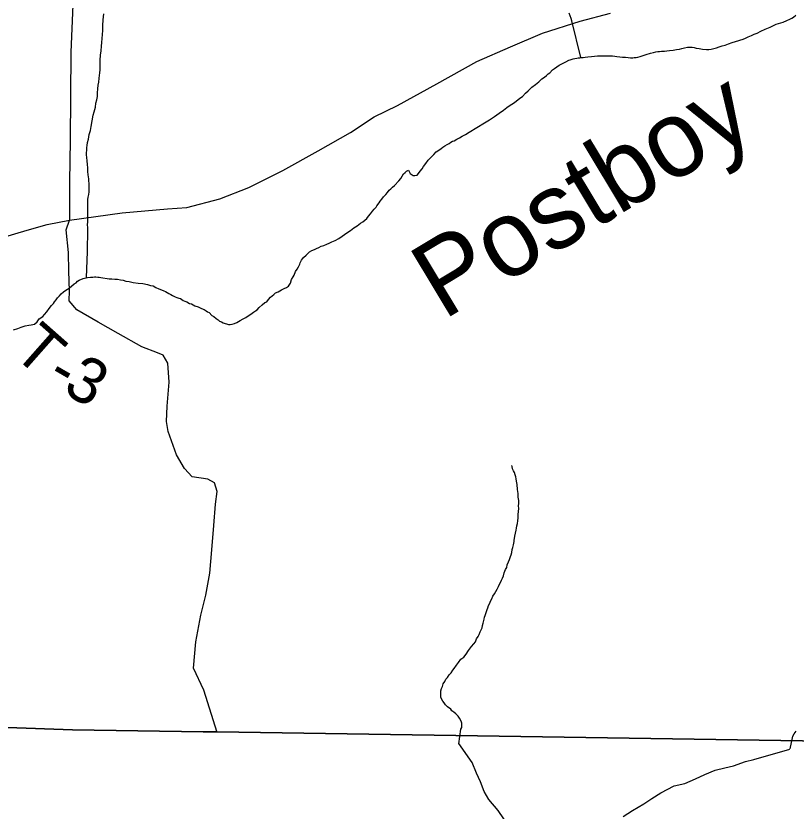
# Model space of a CAD drawing. Extents: x -14196 to 143, y -6096 to 28.
# Drawn here: x 59.622 to 60.591, y 18.723 to 19.711 of the extents above; entities that cross this region are included whole.
import ezdxf

# ---------------------------------------------------------------- set-up
doc = ezdxf.new("R2010")
doc.units = 0
for name, color, linetype in [('GM_X_Corporation', 7, 'Continuous'), ('GM_X_County_Road', 7, 'Continuous'), ('GM_X_Minor_River', 7, 'Continuous'), ('GM_X_Minor_River_Text', 7, 'Continuous'), ('GM_X_Township_Road', 7, 'Continuous'), ('GM_X_Township_Road_Text', 7, 'Continuous')]:
    doc.layers.add(name, color=color, linetype=linetype)

msp = doc.modelspace()

# ---------------------------------------------------------------- linework, layer by layer
at = {"layer": 'GM_X_Corporation'}
for points in [[(58.10282, 23.69854), (58.10282, 18.87106), (58.91817, 18.84869), (59.19654, 18.84209), (59.69267, 18.82448), (59.85497, 18.82206), (59.87217, 18.8218), (60.89542, 18.80611)], [(58.10282, 23.69854), (58.10282, 18.87106), (58.91817, 18.84869), (59.19654, 18.84209), (59.69267, 18.82448), (59.85497, 18.82206), (59.87217, 18.8218), (60.89542, 18.80611)], [(60.89542, 18.80611), (59.87217, 18.8218), (59.85497, 18.82206), (59.69267, 18.82448), (59.19654, 18.84209), (58.91817, 18.84869), (58.10282, 18.87106), (58.10282, 16.89854), (64.90282, 16.89854)], [(60.89542, 18.80611), (59.87217, 18.8218), (59.85497, 18.82206), (59.69267, 18.82448), (59.19654, 18.84209), (58.91817, 18.84869), (58.10282, 18.87106), (58.10282, 16.89854), (62.31172, 16.89854)]]:
    msp.add_lwpolyline(points, dxfattribs=at)
at = {"layer": 'GM_X_County_Road'}
for points in [[(59.69407, 19.75527), (59.69062, 19.66662), (59.6896, 19.55673), (59.68899, 19.50578), (59.68868, 19.45788)], [(59.60114, 19.43513), (59.6362, 19.44515), (59.66109, 19.45224), (59.68868, 19.45788), (59.75416, 19.46676), (59.81062, 19.47161), (59.83451, 19.47336), (59.87562, 19.48428), (59.91135, 19.49848), (59.95373, 19.51931), (59.99754, 19.54398), (60.03799, 19.56667), (60.06712, 19.58602), (60.096, 19.60005), (60.14507, 19.62712), (60.19487, 19.65498), (60.23656, 19.67312), (60.27639, 19.69008), (60.3231, 19.70492), (60.36082, 19.71498)]]:
    msp.add_lwpolyline(points, dxfattribs=at)
at = {"layer": 'GM_X_Minor_River'}
for points in [[(59.70979, 19.38616), (59.71132, 19.41879), (59.71129, 19.42145), (59.71126, 19.42335), (59.71122, 19.42677), (59.71117, 19.43095), (59.71152, 19.43399), (59.71148, 19.43703), (59.71143, 19.44159), (59.71176, 19.44539), (59.71173, 19.44805), (59.7113, 19.45223), (59.71164, 19.45527), (59.71161, 19.45793), (59.71156, 19.46249), (59.71151, 19.46629), (59.71148, 19.46933), (59.71145, 19.47161), (59.71142, 19.47427), (59.71175, 19.47769), (59.71171, 19.48111), (59.71169, 19.48339), (59.71203, 19.48644), (59.71275, 19.48948), (59.71309, 19.49291), (59.71342, 19.49709), (59.71338, 19.50051), (59.71334, 19.50355), (59.71293, 19.5062), (59.7129, 19.50887), (59.71249, 19.51152), (59.71208, 19.51418), (59.71165, 19.51797), (59.71159, 19.52291), (59.71117, 19.52671), (59.71074, 19.53126), (59.7103, 19.53544), (59.70988, 19.53886), (59.70985, 19.54152), (59.7102, 19.54456), (59.71016, 19.54798), (59.71088, 19.55065), (59.71122, 19.55407), (59.71231, 19.55826), (59.71338, 19.56397), (59.71484, 19.56893), (59.71554, 19.57426), (59.71841, 19.58797), (59.7195, 19.59216), (59.72023, 19.59521), (59.72095, 19.59825), (59.72165, 19.6032), (59.72274, 19.60739), (59.72345, 19.6112), (59.72378, 19.61577), (59.7241, 19.62071), (59.72442, 19.62527), (59.72514, 19.62908), (59.72546, 19.63402), (59.72618, 19.63745), (59.72652, 19.64088), (59.72685, 19.64468), (59.7268, 19.64886), (59.72676, 19.65266), (59.72709, 19.65646), (59.7274, 19.66255), (59.72809, 19.66825), (59.7284, 19.67396), (59.72911, 19.67852), (59.72943, 19.68347), (59.72975, 19.68841), (59.73007, 19.69336), (59.73038, 19.69944), (59.73067, 19.70666), (59.73134, 19.71389)], [(60.32369, 19.65972), (60.31251, 19.70536), (60.31172, 19.7084), (60.31054, 19.71142), (60.30936, 19.71483)], [(60.50729, 19.6769), (60.51183, 19.67847), (60.51599, 19.67965), (60.52544, 19.68278), (60.52847, 19.68395), (60.53187, 19.68551), (60.53565, 19.68706), (60.53905, 19.68862), (60.54283, 19.69017), (60.54736, 19.6925), (60.55264, 19.69483), (60.55907, 19.69756), (60.56662, 19.70143), (60.57532, 19.7038), (60.57986, 19.70574), (60.58326, 19.7073), (60.58589, 19.70884), (60.58816, 19.71001), (60.59079, 19.71231)], [(60.15788, 19.55181), (60.16015, 19.55298), (60.16241, 19.55452), (60.16467, 19.55568), (60.16656, 19.55646), (60.16996, 19.5584), (60.17298, 19.55995), (60.17637, 19.56188), (60.18052, 19.5642), (60.18505, 19.56691), (60.20427, 19.5785), (60.2103, 19.58236), (60.21671, 19.58661), (60.22236, 19.59084), (60.22763, 19.59432), (60.23215, 19.59778), (60.23629, 19.60048), (60.24006, 19.60318), (60.24345, 19.60549), (60.24608, 19.6078), (60.24947, 19.61012), (60.25135, 19.61127), (60.2551, 19.61549), (60.25848, 19.61857), (60.26299, 19.62279), (60.26751, 19.62626), (60.27164, 19.62972), (60.2754, 19.63317), (60.27879, 19.63549), (60.28104, 19.63741), (60.2833, 19.63933), (60.28518, 19.64087), (60.28856, 19.64433), (60.29119, 19.64625), (60.29421, 19.64818), (60.29684, 19.65011), (60.30024, 19.65204), (60.30288, 19.65321), (60.30515, 19.65437), (60.30892, 19.65631), (60.31081, 19.65671), (60.31421, 19.65826), (60.31649, 19.65866), (60.31876, 19.65907), (60.32066, 19.65947), (60.32255, 19.65949), (60.32445, 19.65988), (60.32673, 19.65991), (60.32938, 19.66031), (60.33241, 19.66072), (60.33696, 19.66115), (60.34076, 19.66157), (60.34455, 19.66199), (60.34797, 19.66202), (60.35101, 19.66205), (60.36012, 19.66176), (60.36316, 19.66179), (60.3662, 19.66144), (60.36848, 19.66108), (60.37229, 19.66074), (60.37571, 19.66039), (60.37951, 19.66005), (60.38255, 19.6597), (60.3856, 19.65935), (60.38825, 19.65938), (60.39015, 19.65978), (60.39243, 19.6598), (60.3947, 19.6602), (60.39735, 19.66099), (60.40113, 19.66217), (60.40491, 19.66373), (60.41021, 19.6653), (60.414, 19.6661), (60.41702, 19.66688), (60.41968, 19.66729), (60.42158, 19.66731), (60.42423, 19.66772), (60.42765, 19.66775), (60.43068, 19.66816), (60.43409, 19.66858), (60.43865, 19.669), (60.44281, 19.6698), (60.44623, 19.67022), (60.44925, 19.67101), (60.45266, 19.6718), (60.45645, 19.6726), (60.45949, 19.67263), (60.46215, 19.67265), (60.46443, 19.6723), (60.4671, 19.67156), (60.4709, 19.67084), (60.47509, 19.67012), (60.48003, 19.66979), (60.48269, 19.66982), (60.48572, 19.67023), (60.48913, 19.67102), (60.49216, 19.67181), (60.49556, 19.67299), (60.49935, 19.67416), (60.50313, 19.67534), (60.50729, 19.6769)], [(59.88825, 19.3279), (59.8909, 19.32869), (59.89355, 19.32948), (59.89658, 19.33065), (59.90073, 19.33297), (59.9045, 19.33491), (59.9079, 19.33684), (59.91091, 19.33878), (59.91392, 19.34109), (59.91731, 19.3434), (59.91995, 19.34495), (59.92183, 19.34649), (59.92446, 19.34918), (59.92822, 19.35263), (59.9316, 19.35533), (59.93387, 19.35611), (59.93611, 19.35918), (59.93836, 19.36186), (59.94062, 19.36378), (59.9425, 19.36532), (59.94475, 19.36724), (59.94777, 19.3688), (59.95192, 19.37112), (59.95532, 19.37267), (59.95834, 19.37423), (59.96098, 19.37577), (59.96322, 19.37959), (59.96468, 19.38417), (59.96654, 19.38723), (59.96765, 19.38952), (59.9695, 19.39372), (59.97174, 19.39678), (59.97323, 19.39984), (59.97471, 19.40289), (59.97545, 19.4048), (59.97693, 19.40786), (59.97955, 19.4113), (59.98255, 19.41437), (59.9848, 19.4163), (59.98706, 19.41822), (59.98969, 19.42015), (59.9931, 19.42132), (59.99574, 19.42249), (59.99839, 19.42366), (60.00141, 19.4252), (60.00481, 19.42638), (60.00821, 19.42794), (60.01123, 19.42911), (60.01463, 19.43066), (60.01879, 19.4326), (60.02332, 19.43493), (60.02746, 19.43763), (60.03311, 19.44187), (60.03763, 19.44495), (60.04177, 19.44804), (60.04592, 19.45074), (60.05006, 19.45382), (60.05307, 19.45575), (60.05571, 19.45768), (60.05796, 19.45998), (60.06021, 19.46267), (60.06245, 19.46573), (60.06507, 19.4688), (60.06732, 19.47148), (60.06957, 19.47378), (60.07069, 19.47569), (60.0733, 19.47914), (60.07479, 19.48143), (60.07666, 19.48373), (60.07891, 19.4868), (60.08153, 19.48948), (60.08378, 19.49216), (60.08603, 19.49485), (60.0879, 19.49677), (60.09016, 19.49869), (60.09241, 19.50061), (60.09766, 19.50637), (60.10028, 19.50943), (60.10215, 19.51249), (60.10363, 19.51517), (60.10551, 19.51709), (60.10739, 19.51863), (60.10965, 19.51979), (60.11198, 19.51563), (60.11543, 19.51339), (60.11771, 19.51303), (60.12074, 19.51382), (60.12223, 19.51574), (60.12448, 19.51842), (60.12672, 19.52148), (60.12859, 19.52454), (60.1312, 19.52799), (60.13419, 19.5322), (60.13794, 19.53603), (60.14132, 19.53949), (60.14432, 19.54256), (60.14771, 19.54487), (60.15035, 19.5468), (60.15261, 19.54834), (60.15487, 19.54988), (60.15788, 19.55181)], [(59.61943, 19.3213), (59.62473, 19.32326), (59.62888, 19.32482), (59.6338, 19.32639), (59.63835, 19.3272), (59.64138, 19.32761), (59.64328, 19.32801), (59.64555, 19.32842), (59.64855, 19.33149), (59.65117, 19.33531), (59.65569, 19.33802), (59.65794, 19.34033), (59.66056, 19.34377), (59.66355, 19.34799), (59.66654, 19.35182), (59.66879, 19.35412), (59.67029, 19.35641), (59.67216, 19.35872), (59.67402, 19.36139), (59.67627, 19.3637), (59.67853, 19.366), (59.68153, 19.36869), (59.68417, 19.37062), (59.68643, 19.37216), (59.68831, 19.37332), (59.69471, 19.37871), (59.69697, 19.37988), (59.69885, 19.38179), (59.70073, 19.38295), (59.70564, 19.38528), (59.71133, 19.38649), (59.71474, 19.3869), (59.71778, 19.38693), (59.71967, 19.38733), (59.72157, 19.38735), (59.72385, 19.387), (59.72575, 19.38702), (59.72766, 19.38627), (59.73793, 19.38486), (59.74135, 19.3849), (59.74515, 19.38456), (59.74857, 19.38421), (59.752, 19.38349), (59.75542, 19.38314), (59.75885, 19.38204), (59.76304, 19.38133), (59.76799, 19.38024), (59.77408, 19.37954), (59.77978, 19.37884), (59.78549, 19.37776), (59.7893, 19.37666), (59.79273, 19.37593), (59.79617, 19.37407), (59.79961, 19.37259), (59.80304, 19.3711), (59.80609, 19.36999), (59.80801, 19.36887), (59.80992, 19.36775), (59.81221, 19.36663), (59.81451, 19.36514), (59.8168, 19.36402), (59.81986, 19.36253), (59.82214, 19.3618), (59.82481, 19.36069), (59.82672, 19.36033), (59.82978, 19.35808), (59.83208, 19.35696), (59.83436, 19.35623), (59.8378, 19.35436), (59.84047, 19.35363), (59.84468, 19.35139), (59.84849, 19.34991), (59.85269, 19.34806), (59.85613, 19.34657), (59.85842, 19.34507), (59.86034, 19.34395), (59.86225, 19.34283), (59.86571, 19.33945), (59.868, 19.33795), (59.87107, 19.33533), (59.87337, 19.33383), (59.87529, 19.33233), (59.87758, 19.33121), (59.87949, 19.33009), (59.88635, 19.32827), (59.88825, 19.3279)], [(60.24459, 19.1294), (60.24416, 19.13358), (60.24375, 19.13623), (60.24295, 19.13888), (60.24217, 19.14115), (60.24137, 19.14419), (60.2402, 19.14645), (60.23904, 19.14872), (60.23862, 19.15176), (60.23823, 19.15251), (60.23823, 19.15289)], [(60.17231, 18.80698), (60.17494, 18.82513), (60.17605, 18.82742), (60.17602, 18.82932), (60.17598, 18.83274), (60.17519, 18.83539), (60.17325, 18.83879), (60.1717, 18.84143), (60.16863, 18.84444), (60.16633, 18.84632), (60.16365, 18.84819), (60.16248, 18.85008), (60.15827, 18.85308), (60.15558, 18.85571), (60.15403, 18.85797), (60.15249, 18.86024), (60.15015, 18.86477), (60.15006, 18.87275), (60.15078, 18.87579), (60.15189, 18.87846), (60.15299, 18.88151), (60.15485, 18.88457), (60.15634, 18.88725), (60.15821, 18.88955), (60.16045, 18.89299), (60.1627, 18.89529), (60.16494, 18.89873), (60.16644, 18.90065), (60.16942, 18.90486), (60.17204, 18.90792), (60.17503, 18.91213), (60.17842, 18.91483), (60.18141, 18.91866), (60.1844, 18.92287), (60.18813, 18.92784), (60.19113, 18.93129), (60.193, 18.93397), (60.19448, 18.93741), (60.19634, 18.94046), (60.19745, 18.94276), (60.19893, 18.94619), (60.20004, 18.94886), (60.20153, 18.95115), (60.20187, 18.9542), (60.2026, 18.95686), (60.20296, 18.95877), (60.20368, 18.96181), (60.20441, 18.96448), (60.20514, 18.96639), (60.20587, 18.96905), (60.2066, 18.97134), (60.20771, 18.97401), (60.20845, 18.97592), (60.20917, 18.97897), (60.21065, 18.98202), (60.21176, 18.98431), (60.21325, 18.98737), (60.21473, 18.99042), (60.21659, 18.99348), (60.21846, 18.99616), (60.21994, 18.99921), (60.22142, 19.00265), (60.22551, 19.01029), (60.22661, 19.01296), (60.22772, 19.01563), (60.22844, 19.01943), (60.23028, 19.02363), (60.23177, 19.02631), (60.23249, 19.02935), (60.23397, 19.03317), (60.23545, 19.03622), (60.23655, 19.03965), (60.23728, 19.04194), (60.238, 19.04499), (60.23872, 19.04841), (60.23945, 19.05108), (60.24017, 19.05451), (60.24088, 19.05831), (60.24124, 19.06022), (60.24159, 19.06212), (60.24194, 19.06516), (60.24265, 19.06897), (60.24337, 19.0724), (60.2441, 19.07506), (60.24445, 19.07773), (60.24517, 19.08077), (60.24551, 19.0842), (60.24622, 19.088), (60.24617, 19.09218), (60.24651, 19.09561), (60.24685, 19.09941), (60.24642, 19.10282), (60.24677, 19.10549), (60.24673, 19.10929), (60.24592, 19.11346), (60.24586, 19.11802), (60.24505, 19.12295), (60.24459, 19.1294)], [(60.58382, 18.80081), (60.58709, 18.81677), (60.58896, 18.81945), (60.5912, 18.82289)], [(60.27951, 18.62107), (60.26605, 18.63138), (60.2599, 18.64271), (60.24958, 18.65515), (60.24267, 18.66572), (60.23688, 18.67971), (60.23563, 18.69411), (60.23403, 18.70396), (60.22827, 18.71378), (60.22099, 18.72434), (60.20952, 18.73791), (60.20376, 18.74773), (60.19912, 18.75984), (60.19412, 18.77042), (60.18871, 18.78366), (60.17235, 18.80727)], [(60.3763, 18.71674), (60.38798, 18.72402), (60.40193, 18.73247), (60.41209, 18.73899), (60.4234, 18.74627), (60.43961, 18.75473), (60.45322, 18.75786), (60.46642, 18.76364), (60.47774, 18.76903), (60.49057, 18.77443), (60.50266, 18.77717), (60.51362, 18.7799), (60.52835, 18.78494), (60.53855, 18.78766), (60.58361, 18.80059)]]:
    msp.add_lwpolyline(points, dxfattribs=at)
at = {"layer": 'GM_X_Township_Road'}
msp.add_lwpolyline([(59.87237, 18.82126), (59.85553, 18.87374), (59.8429, 18.90117), (59.84587, 18.93393), (59.85187, 18.96677), (59.85808, 18.99162), (59.86308, 19.01912), (59.86577, 19.04807), (59.86804, 19.07815), (59.87003, 19.1048), (59.87229, 19.12045), (59.86898, 19.13139), (59.86051, 19.13573), (59.84107, 19.13866), (59.83169, 19.14906), (59.82176, 19.16629), (59.81154, 19.19492), (59.80933, 19.20741), (59.80998, 19.22643), (59.81264, 19.25652), (59.81091, 19.28005), (59.80535, 19.28979), (59.79804, 19.29302), (59.77849, 19.30051), (59.74921, 19.31688), (59.72454, 19.33108), (59.69795, 19.34636), (59.68855, 19.35753), (59.68862, 19.37007), (59.688, 19.39439), (59.68742, 19.41756), (59.68481, 19.44562), (59.68868, 19.45788)], dxfattribs=at)

# ---------------------------------------------------------------- texts
at = {"layer": 'GM_X_Minor_River_Text'}
msp.add_text('Postboy', height=0.09465, rotation=31.0201, dxfattribs=at).set_placement((60.15308, 19.33285))
at = {"layer": 'GM_X_Township_Road_Text'}
for s, rotation, p in [('T', 318.56292, (59.61635, 19.29153)), ('3', 330.25485, (59.67869, 19.2444)), ('-', 330.03352, (59.65827, 19.25618))]:
    msp.add_text(s, height=0.05682, rotation=rotation, dxfattribs=at).set_placement(p)

doc.saveas('drawing.dxf')
